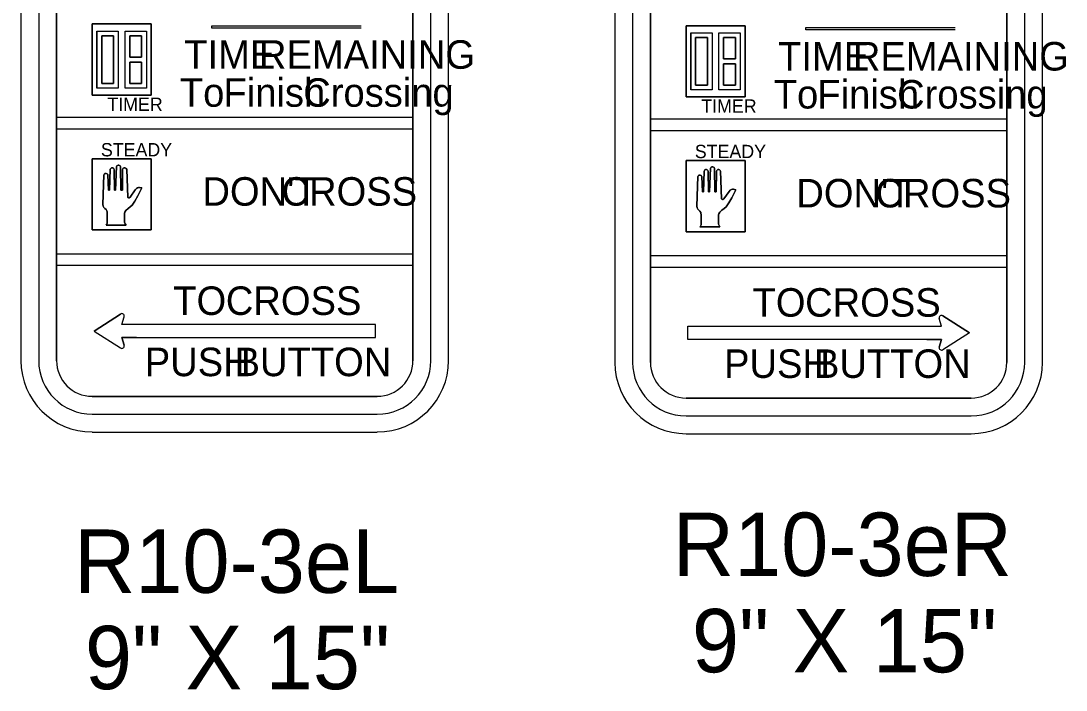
# Model space of a CAD drawing. Extents: x 0 to 3.01, y -0.05 to 1.83.
# Drawn here: x 1.3042 to 1.4417, y 1.5352 to 1.6233 of the extents above; entities that cross this region are included whole.
import ezdxf

# ---------------------------------------------------------------- set-up
doc = ezdxf.new("R2010")
doc.units = 0
doc.layers.add('TR_TS_Text', color=7, linetype='Continuous')

msp = doc.modelspace()

# ---------------------------------------------------------------- linework, layer by layer
at = {"layer": 'TR_TS_Text'}
for p, q in [((1.30652, 1.6536), (1.30652, 1.57854)), ((1.30887, 1.57854), (1.30887, 1.6536)), ((1.35578, 1.6536), (1.35578, 1.57854)), ((1.35813, 1.57854), (1.35813, 1.6536)), ((1.38469, 1.65337), (1.38469, 1.57831)), ((1.38704, 1.57831), (1.38704, 1.65337)), ((1.43395, 1.65337), (1.43395, 1.57831)), ((1.4363, 1.57831), (1.4363, 1.65337)), ((1.32931, 1.62263), (1.34898, 1.62263)), ((1.32931, 1.62232), (1.32931, 1.62263)), ((1.34898, 1.62232), (1.32931, 1.62232)), ((1.40748, 1.6224), (1.42715, 1.6224)), ((1.40748, 1.62209), (1.40748, 1.6224)), ((1.42715, 1.62209), (1.40748, 1.62209)), ((1.31419, 1.62192), (1.31419, 1.61441)), ((1.39236, 1.62169), (1.39236, 1.61418)), ((1.30887, 1.61059), (1.35578, 1.61059)), ((1.30887, 1.60903), (1.30887, 1.61059)), ((1.38704, 1.61036), (1.43395, 1.61036)), ((1.38704, 1.6088), (1.38704, 1.61036)), ((1.35578, 1.60903), (1.30887, 1.60903)), ((1.43395, 1.6088), (1.38704, 1.6088)), ((1.30887, 1.59261), (1.35578, 1.59261)), ((1.30887, 1.59105), (1.30887, 1.59261)), ((1.38704, 1.59238), (1.43395, 1.59238)), ((1.38704, 1.59082), (1.38704, 1.59238)), ((1.35578, 1.59105), (1.30887, 1.59105)), ((1.43395, 1.59082), (1.38704, 1.59082)), ((1.3138, 1.58244), (1.3173, 1.58468)), ((1.31746, 1.58332), (1.31776, 1.58433)), ((1.42537, 1.58309), (1.42506, 1.5841)), ((1.42902, 1.58221), (1.42552, 1.58445)), ((1.3138, 1.58244), (1.3173, 1.58021)), ((1.3194, 1.58332), (1.31746, 1.58332)), ((1.42342, 1.58309), (1.42537, 1.58309)), ((1.42902, 1.58221), (1.42552, 1.57998)), ((1.3194, 1.58157), (1.31746, 1.58157)), ((1.31746, 1.58157), (1.31776, 1.58056)), ((1.42342, 1.58134), (1.42537, 1.58134)), ((1.42537, 1.58134), (1.42506, 1.58033)), ((1.35109, 1.57384), (1.31356, 1.57384)), ((1.42926, 1.57361), (1.39173, 1.57361)), ((1.31356, 1.5715), (1.35109, 1.5715)), ((1.39173, 1.57127), (1.42926, 1.57127))]:
    msp.add_line(p, q, dxfattribs=at)
for points in [[(1.30418, 1.6536), (1.30418, 1.57854)], [(1.30652, 1.6536), (1.30652, 1.57854)], [(1.30887, 1.6536), (1.30887, 1.57854)], [(1.35578, 1.57854), (1.35578, 1.6536)], [(1.35813, 1.57854), (1.35813, 1.6536)], [(1.36047, 1.57854), (1.36047, 1.6536)], [(1.38235, 1.65337), (1.38235, 1.57831)], [(1.38469, 1.65337), (1.38469, 1.57831)], [(1.38704, 1.65337), (1.38704, 1.57831)], [(1.43395, 1.57831), (1.43395, 1.65337)], [(1.4363, 1.57831), (1.4363, 1.65337)], [(1.43864, 1.57831), (1.43864, 1.65337)], [(1.31356, 1.61348), (1.32132, 1.61348), (1.32132, 1.62286), (1.31356, 1.62286), (1.31356, 1.61348)], [(1.39173, 1.61325), (1.39949, 1.61325), (1.39949, 1.62263), (1.39173, 1.62263), (1.39173, 1.61325)], [(1.31419, 1.62192), (1.317, 1.62192), (1.317, 1.61441), (1.31419, 1.61441), (1.31419, 1.62192)], [(1.31481, 1.61504), (1.31638, 1.61504), (1.31638, 1.62129), (1.31481, 1.62129), (1.31481, 1.61504)], [(1.31788, 1.62192), (1.32069, 1.62192), (1.32069, 1.61441), (1.31788, 1.61441), (1.31788, 1.62192)], [(1.3185, 1.61848), (1.32007, 1.61848), (1.32007, 1.62129), (1.3185, 1.62129), (1.3185, 1.61848)], [(1.39236, 1.62169), (1.39517, 1.62169), (1.39517, 1.61418), (1.39236, 1.61418), (1.39236, 1.62169)], [(1.39298, 1.61481), (1.39455, 1.61481), (1.39455, 1.62107), (1.39298, 1.62107), (1.39298, 1.61481)], [(1.39605, 1.62169), (1.39886, 1.62169), (1.39886, 1.61418), (1.39605, 1.61418), (1.39605, 1.62169)], [(1.39667, 1.61825), (1.39824, 1.61825), (1.39824, 1.62107), (1.39667, 1.62107), (1.39667, 1.61825)], [(1.32007, 1.61785), (1.3185, 1.61785), (1.3185, 1.61504), (1.32007, 1.61504), (1.32007, 1.61785)], [(1.39824, 1.61762), (1.39667, 1.61762), (1.39667, 1.61481), (1.39824, 1.61481), (1.39824, 1.61762)], [(1.31356, 1.59574), (1.32132, 1.59574), (1.32132, 1.60512), (1.31356, 1.60512), (1.31356, 1.59574)], [(1.31538, 1.59638), (1.31802, 1.59638), (1.31791, 1.59654), (1.31783, 1.59675), (1.31782, 1.59795), (1.31787, 1.59809), (1.31801, 1.5983), (1.31828, 1.59856), (1.31856, 1.59881), (1.31883, 1.59903), (1.31901, 1.59928), (1.31919, 1.59955), (1.31957, 1.60022), (1.3201, 1.60127), (1.31995, 1.60131), (1.31979, 1.60133), (1.31966, 1.60133), (1.31954, 1.6013), (1.31938, 1.60121), (1.31921, 1.60103), (1.31855, 1.60008), (1.31844, 1.59999), (1.3184, 1.59997), (1.31834, 1.59997), (1.31826, 1.60003), (1.31824, 1.60006), (1.31811, 1.6037), (1.31805, 1.60382), (1.31796, 1.60389), (1.31789, 1.60392), (1.31775, 1.60392), (1.31766, 1.60386), (1.3176, 1.6038), (1.31756, 1.60371), (1.31753, 1.60098), (1.31735, 1.60098), (1.31729, 1.60409), (1.31724, 1.60418), (1.31716, 1.60425), (1.31708, 1.60428), (1.31697, 1.60429), (1.31688, 1.60425), (1.3168, 1.60417), (1.31676, 1.60409), (1.31664, 1.60098), (1.31651, 1.60098), (1.31647, 1.60371), (1.31642, 1.60381), (1.31635, 1.60388), (1.31626, 1.60392), (1.31611, 1.60392), (1.31604, 1.60387), (1.31597, 1.60381), (1.31593, 1.60373), (1.31586, 1.60098), (1.31572, 1.60098), (1.31563, 1.60299), (1.3156, 1.60306), (1.31553, 1.60314), (1.31541, 1.60319), (1.31531, 1.60319), (1.31524, 1.60317), (1.31519, 1.60313), (1.31513, 1.60306), (1.31509, 1.60299), (1.31498, 1.5991), (1.31501, 1.59889), (1.31511, 1.5987), (1.31524, 1.59856), (1.31539, 1.59843), (1.31549, 1.59827), (1.31552, 1.59813), (1.31555, 1.59803), (1.31553, 1.59666), (1.31547, 1.59649), (1.31538, 1.59638)], [(1.31547, 1.59649), (1.31553, 1.59666), (1.31555, 1.59803), (1.31552, 1.59813), (1.31549, 1.59827), (1.31539, 1.59843), (1.31524, 1.59856), (1.31511, 1.5987), (1.31501, 1.59889), (1.31498, 1.5991), (1.31509, 1.60299), (1.31513, 1.60306), (1.31519, 1.60313), (1.31524, 1.60317), (1.31531, 1.60319), (1.31541, 1.60319), (1.31553, 1.60314), (1.3156, 1.60306), (1.31563, 1.60299), (1.31572, 1.60098), (1.31586, 1.60098), (1.31593, 1.60373), (1.31597, 1.60381), (1.31604, 1.60387), (1.31611, 1.60392), (1.31626, 1.60392), (1.31635, 1.60388), (1.31642, 1.60381), (1.31647, 1.60371), (1.31651, 1.60098), (1.31664, 1.60098), (1.31676, 1.60409), (1.3168, 1.60417), (1.31688, 1.60425), (1.31697, 1.60429), (1.31708, 1.60428), (1.31716, 1.60425), (1.31724, 1.60418), (1.31729, 1.60409), (1.31735, 1.60098), (1.31753, 1.60098), (1.31756, 1.60371), (1.3176, 1.6038), (1.31766, 1.60386), (1.31775, 1.60392), (1.31789, 1.60392), (1.31796, 1.60389), (1.31805, 1.60382), (1.31811, 1.6037), (1.31824, 1.60006), (1.31826, 1.60003), (1.31834, 1.59997), (1.3184, 1.59997), (1.31844, 1.59999), (1.31855, 1.60008), (1.31921, 1.60103), (1.31938, 1.60121), (1.31954, 1.6013), (1.31966, 1.60133), (1.31979, 1.60133), (1.31995, 1.60131), (1.3201, 1.60127), (1.31957, 1.60022), (1.31919, 1.59955), (1.31901, 1.59928), (1.31883, 1.59903), (1.31856, 1.59881), (1.31828, 1.59856), (1.31801, 1.5983), (1.31787, 1.59809), (1.31782, 1.59795), (1.31783, 1.59675), (1.31791, 1.59654), (1.31802, 1.59638), (1.31538, 1.59638), (1.31547, 1.59649)], [(1.39173, 1.59551), (1.39949, 1.59551), (1.39949, 1.60489), (1.39173, 1.60489), (1.39173, 1.59551)], [(1.39355, 1.59615), (1.39619, 1.59615), (1.39608, 1.59631), (1.396, 1.59652), (1.39599, 1.59773), (1.39604, 1.59786), (1.39618, 1.59807), (1.39645, 1.59834), (1.39673, 1.59858), (1.397, 1.5988), (1.39718, 1.59905), (1.39736, 1.59932), (1.39774, 1.59999), (1.39827, 1.60104), (1.39812, 1.60108), (1.39796, 1.6011), (1.39783, 1.6011), (1.39771, 1.60107), (1.39755, 1.60098), (1.39738, 1.6008), (1.39672, 1.59985), (1.39661, 1.59976), (1.39657, 1.59974), (1.39651, 1.59974), (1.39643, 1.5998), (1.39641, 1.59983), (1.39628, 1.60347), (1.39622, 1.60359), (1.39613, 1.60366), (1.39606, 1.60369), (1.39592, 1.60369), (1.39583, 1.60363), (1.39577, 1.60357), (1.39573, 1.60348), (1.3957, 1.60075), (1.39552, 1.60075), (1.39546, 1.60386), (1.39541, 1.60395), (1.39533, 1.60402), (1.39525, 1.60406), (1.39514, 1.60406), (1.39505, 1.60402), (1.39497, 1.60394), (1.39493, 1.60386), (1.39481, 1.60075), (1.39468, 1.60075), (1.39464, 1.60348), (1.39459, 1.60358), (1.39452, 1.60365), (1.39443, 1.60369), (1.39428, 1.60369), (1.39421, 1.60364), (1.39414, 1.60358), (1.3941, 1.6035), (1.39403, 1.60075), (1.3939, 1.60075), (1.3938, 1.60276), (1.39377, 1.60283), (1.3937, 1.60291), (1.39358, 1.60296), (1.39348, 1.60296), (1.39341, 1.60294), (1.39336, 1.6029), (1.3933, 1.60284), (1.39326, 1.60276), (1.39315, 1.59887), (1.39318, 1.59866), (1.39328, 1.59847), (1.39341, 1.59833), (1.39356, 1.5982), (1.39366, 1.59804), (1.39369, 1.5979), (1.39372, 1.5978), (1.3937, 1.59643), (1.39364, 1.59626), (1.39355, 1.59615)], [(1.39364, 1.59626), (1.3937, 1.59643), (1.39372, 1.5978), (1.39369, 1.5979), (1.39366, 1.59804), (1.39356, 1.5982), (1.39341, 1.59833), (1.39328, 1.59847), (1.39318, 1.59866), (1.39315, 1.59887), (1.39326, 1.60276), (1.3933, 1.60284), (1.39336, 1.6029), (1.39341, 1.60294), (1.39348, 1.60296), (1.39358, 1.60296), (1.3937, 1.60291), (1.39377, 1.60283), (1.3938, 1.60276), (1.3939, 1.60075), (1.39403, 1.60075), (1.3941, 1.6035), (1.39414, 1.60358), (1.39421, 1.60364), (1.39428, 1.60369), (1.39443, 1.60369), (1.39452, 1.60365), (1.39459, 1.60358), (1.39464, 1.60348), (1.39468, 1.60075), (1.39481, 1.60075), (1.39493, 1.60386), (1.39497, 1.60394), (1.39505, 1.60402), (1.39514, 1.60406), (1.39525, 1.60406), (1.39533, 1.60402), (1.39541, 1.60395), (1.39546, 1.60386), (1.39552, 1.60075), (1.3957, 1.60075), (1.39573, 1.60348), (1.39577, 1.60357), (1.39583, 1.60363), (1.39592, 1.60369), (1.39606, 1.60369), (1.39613, 1.60366), (1.39622, 1.60359), (1.39628, 1.60347), (1.39641, 1.59983), (1.39643, 1.5998), (1.39651, 1.59974), (1.39657, 1.59974), (1.39661, 1.59976), (1.39672, 1.59985), (1.39738, 1.6008), (1.39755, 1.60098), (1.39771, 1.60107), (1.39783, 1.6011), (1.39796, 1.6011), (1.39812, 1.60108), (1.39827, 1.60104), (1.39774, 1.59999), (1.39736, 1.59932), (1.39718, 1.59905), (1.397, 1.5988), (1.39673, 1.59858), (1.39645, 1.59834), (1.39618, 1.59807), (1.39604, 1.59786), (1.39599, 1.59773), (1.396, 1.59652), (1.39608, 1.59631), (1.39619, 1.59615), (1.39355, 1.59615), (1.39364, 1.59626)], [(1.3173, 1.58468), (1.3138, 1.58244), (1.3173, 1.58021)], [(1.35085, 1.58332), (1.31746, 1.58332), (1.31776, 1.58433)], [(1.39197, 1.58309), (1.42537, 1.58309), (1.42506, 1.5841)], [(1.42552, 1.58445), (1.42902, 1.58221), (1.42552, 1.57998)], [(1.31776, 1.58056), (1.31746, 1.58157), (1.35085, 1.58157), (1.35085, 1.58332)], [(1.42506, 1.58033), (1.42537, 1.58134), (1.39197, 1.58134), (1.39197, 1.58309)], [(1.31356, 1.57384), (1.35109, 1.57384)], [(1.39173, 1.57361), (1.42926, 1.57361)], [(1.31356, 1.5715), (1.35109, 1.5715)], [(1.39173, 1.57127), (1.42926, 1.57127)], [(1.31356, 1.56915), (1.35109, 1.56915)], [(1.39173, 1.56892), (1.42926, 1.56892)]]:
    msp.add_lwpolyline(points, dxfattribs=at)
for points in [[(1.31356, 1.62286), (1.32132, 1.62286), (1.32132, 1.61348), (1.31356, 1.61348)], [(1.39173, 1.62263), (1.39949, 1.62263), (1.39949, 1.61325), (1.39173, 1.61325)], [(1.31419, 1.62192), (1.317, 1.62192), (1.317, 1.61441), (1.31419, 1.61441)], [(1.31481, 1.62129), (1.31638, 1.62129), (1.31638, 1.61504), (1.31481, 1.61504)], [(1.31788, 1.62192), (1.32069, 1.62192), (1.32069, 1.61441), (1.31788, 1.61441)], [(1.3185, 1.62129), (1.32007, 1.62129), (1.32007, 1.61848), (1.3185, 1.61848)], [(1.39236, 1.62169), (1.39517, 1.62169), (1.39517, 1.61418), (1.39236, 1.61418)], [(1.39298, 1.62107), (1.39455, 1.62107), (1.39455, 1.61481), (1.39298, 1.61481)], [(1.39605, 1.62169), (1.39886, 1.62169), (1.39886, 1.61418), (1.39605, 1.61418)], [(1.39667, 1.62107), (1.39824, 1.62107), (1.39824, 1.61825), (1.39667, 1.61825)], [(1.32007, 1.61504), (1.3185, 1.61504), (1.3185, 1.61785), (1.32007, 1.61785)], [(1.39824, 1.61481), (1.39667, 1.61481), (1.39667, 1.61762), (1.39824, 1.61762)], [(1.31356, 1.60512), (1.32132, 1.60512), (1.32132, 1.59574), (1.31356, 1.59574)], [(1.39173, 1.60489), (1.39949, 1.60489), (1.39949, 1.59551), (1.39173, 1.59551)]]:
    msp.add_lwpolyline(points, close=True, dxfattribs=at)
for centre, radius, start, end in [((1.31747, 1.58442), 0.000308, 343, 122.5), ((1.31747, 1.58442), 0.000308, 343, 122.5), ((1.42535, 1.58419), 0.000308, 57.5, 197), ((1.42535, 1.58419), 0.000308, 57.5, 197), ((1.31747, 1.58047), 0.000308, 237.5, 17), ((1.31747, 1.58047), 0.000308, 237.5, 17), ((1.42535, 1.58024), 0.000308, 163, 302.5), ((1.42535, 1.58024), 0.000308, 163, 302.5), ((1.31356, 1.57854), 0.00938, 180, 270), ((1.31356, 1.57854), 0.00704, 180, 270), ((1.31356, 1.57854), 0.00704, 180, 270), ((1.31356, 1.57854), 0.00469, 180, 270), ((1.31356, 1.57854), 0.00469, 180, 270), ((1.35109, 1.57854), 0.00938, 270, 360), ((1.35109, 1.57854), 0.00704, 270, 360), ((1.35109, 1.57854), 0.00469, 270, 360), ((1.35109, 1.57854), 0.00704, 270, 360), ((1.35109, 1.57854), 0.00469, 270, 360), ((1.39173, 1.57831), 0.00938, 180, 270), ((1.39173, 1.57831), 0.00704, 180, 270), ((1.39173, 1.57831), 0.00704, 180, 270), ((1.39173, 1.57831), 0.00469, 180, 270), ((1.39173, 1.57831), 0.00469, 180, 270), ((1.42926, 1.57831), 0.00938, 270, 360), ((1.42926, 1.57831), 0.00704, 270, 360), ((1.42926, 1.57831), 0.00469, 270, 360), ((1.42926, 1.57831), 0.00704, 270, 360), ((1.42926, 1.57831), 0.00469, 270, 360)]:
    msp.add_arc(centre, radius, start, end, dxfattribs=at)

# ---------------------------------------------------------------- texts
for s, height, p in [('TIME', 0.003753, (1.32567, 1.61696)), ('REMAINING', 0.003753, (1.33551, 1.61696)), ('TIME', 0.003753, (1.40384, 1.61673)), ('REMAINING', 0.003753, (1.41368, 1.61673)), ('To', 0.003753, (1.3251, 1.61196)), ('Finish', 0.003753, (1.33084, 1.61196)), ('Crossing', 0.003753, (1.34134, 1.61196)), ('To', 0.003753, (1.40327, 1.61173)), ('Finish', 0.003753, (1.40901, 1.61173)), ('Crossing', 0.003753, (1.41951, 1.61173)), ('TIMER', 0.001751, (1.31556, 1.61141)), ('TIMER', 0.001751, (1.39373, 1.61118)), ('STEADY', 0.001751, (1.31471, 1.60543)), ('STEADY', 0.001751, (1.39288, 1.6052)), ("DON'T", 0.003753, (1.32807, 1.59894)), ('CROSS', 0.003753, (1.33848, 1.59894)), ("DON'T", 0.003753, (1.40624, 1.59871)), ('CROSS', 0.003753, (1.41665, 1.59871)), ('TO', 0.003753, (1.32423, 1.58456)), ('CROSS', 0.003753, (1.33115, 1.58456)), ('TO', 0.003753, (1.40048, 1.58433)), ('CROSS', 0.003753, (1.4074, 1.58433)), ('PUSH', 0.003753, (1.32048, 1.5765)), ('BUTTON', 0.003753, (1.3323, 1.5765)), ('PUSH', 0.003753, (1.39673, 1.57627)), ('BUTTON', 0.003753, (1.40856, 1.57627)), ('R10-3eR', 0.00834, (1.38999, 1.5502)), ('R10-3eL', 0.00834, (1.31118, 1.54798)), ('9" X 15"', 0.00834, (1.3925, 1.53752)), ('9" X 15"', 0.00834, (1.3126, 1.5353))]:
    msp.add_text(s, height=height, rotation=360, dxfattribs=at).set_placement(p)

doc.saveas('drawing.dxf')
